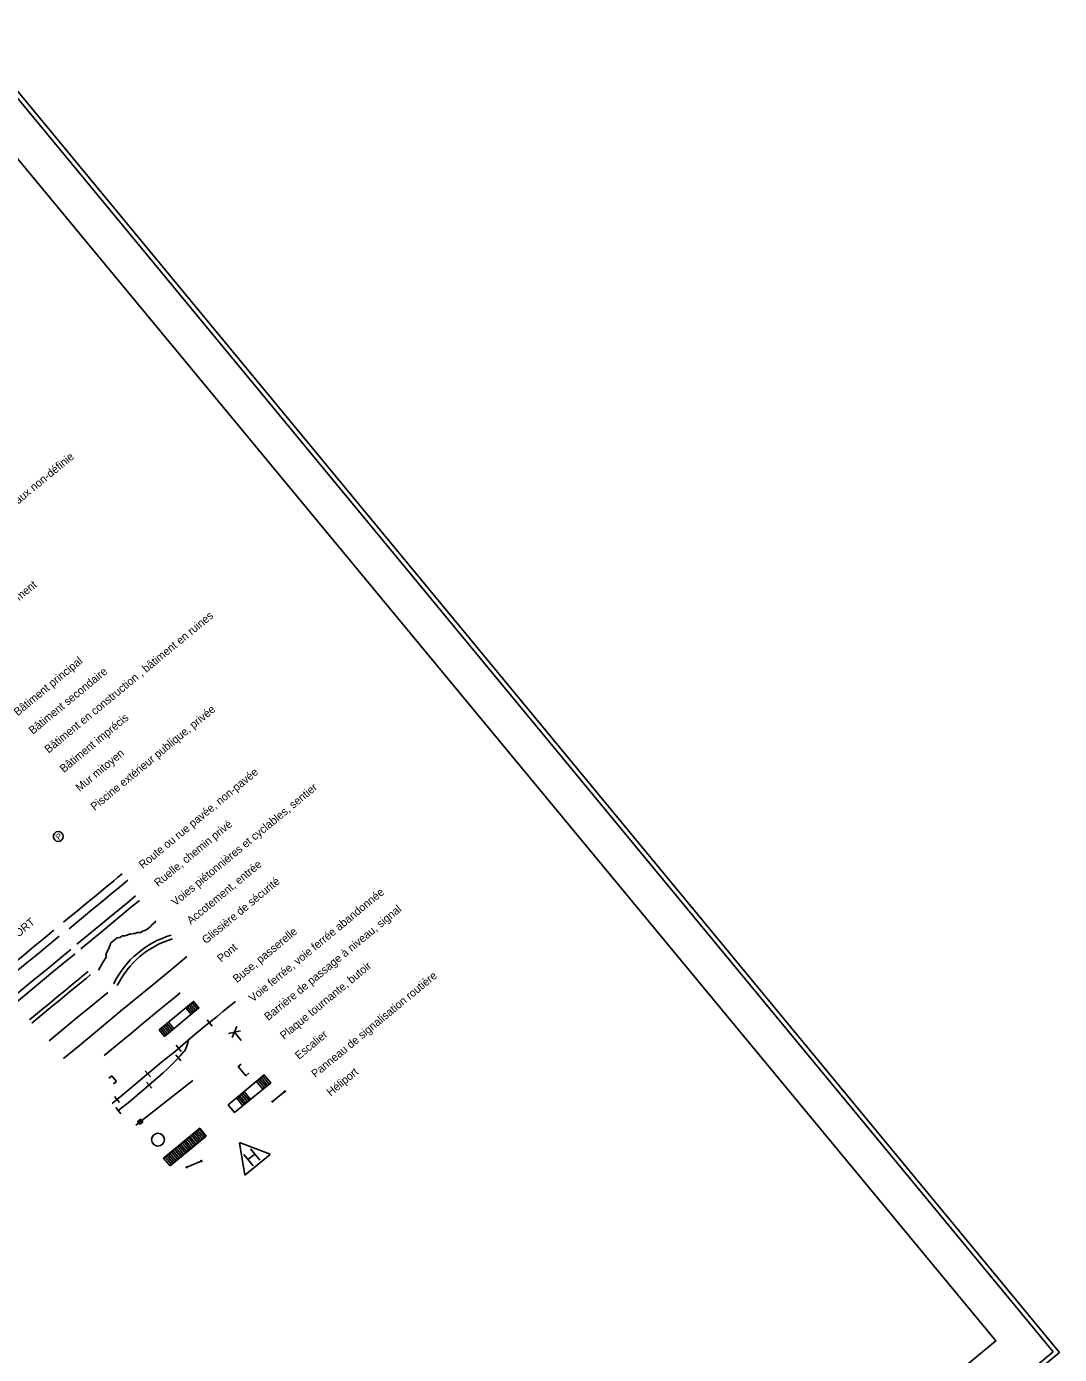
# Model space of a CAD drawing. Extents: x 347059 to 352153, y 6073752 to 6078601.
# Drawn here: x 351379 to 352153, y 6076585 to 6077580 of the extents above; entities that cross this region are included whole.
import ezdxf

# ---------------------------------------------------------------- set-up
doc = ezdxf.new("R2010")
doc.units = 0
for name, color, linetype in [('Level 15', 7, 'Continuous'), ('Level 19', 7, 'Continuous'), ('Level 21', 7, 'Continuous'), ('Level 22', 7, 'Continuous'), ('Level 23', 7, 'Continuous'), ('Level 25', 7, 'Continuous'), ('Level 26', 7, 'Continuous'), ('Level 38', 7, 'Continuous'), ('Level 60', 7, 'Continuous'), ('Level 63', 7, 'Continuous')]:
    doc.layers.add(name, color=color, linetype=linetype)

msp = doc.modelspace()

# ---------------------------------------------------------------- linework, layer by layer
at = {"layer": 'Level 15'}
for p, q in [((351563.37, 6076774.08), (351572.52, 6076781.65)), ((351498.98, 6076724.83), (351509.94, 6076729.48))]:
    msp.add_line(p, q, dxfattribs=at)
for points in [[(351572.46, 6076781.08), (351573.09, 6076781.58), (351572.59, 6076782.19), (351571.95, 6076781.68)], [(351563.3, 6076773.54), (351563.91, 6076774.01), (351563.43, 6076774.62), (351562.8, 6076774.11)], [(351498.77, 6076724.32), (351499.49, 6076724.62), (351499.19, 6076725.34), (351498.47, 6076725.04)], [(351509.73, 6076728.97), (351510.45, 6076729.26), (351510.15, 6076729.98), (351509.4, 6076729.69)]]:
    msp.add_lwpolyline(points, close=True, dxfattribs=at)
at = {"layer": 'Level 19'}
for points in [[(351416.66, 6076891.99), (351430.35, 6076903.36), (351444.34, 6076914.82), (351455.03, 6076923.64), (351460.68, 6076928.3)], [(351419.57, 6076888.48), (351433.26, 6076899.85), (351447.16, 6076911.37), (351457.88, 6076920.19), (351463.5, 6076924.76)]]:
    msp.add_lwpolyline(points, dxfattribs=at)
for radius in [70.21, 67.21]:
    msp.add_arc((351507.33, 6076831.56), radius, 106.46205, 153.98293, dxfattribs=at)
at = {"layer": 'Level 21'}
for points in [[(351406.57, 6076908.48), (351411.22, 6076912.28), (351415.85, 6076916.14), (351423.61, 6076922.53), (351431.32, 6076928.91), (351437.81, 6076934.26), (351444.37, 6076939.66), (351447.42, 6076942.21), (351450.54, 6076944.77)], [(351410.94, 6076903.68), (351415.56, 6076907.54), (351420.22, 6076911.34), (351427.95, 6076917.72), (351435.63, 6076924.07), (351442.18, 6076929.48), (351448.65, 6076934.88), (351451.76, 6076937.44), (351454.87, 6076940.02)], [(351355.35, 6076866.17), (351361, 6076870.87), (351366.69, 6076875.59), (351375.27, 6076882.65), (351383.88, 6076889.75), (351391.55, 6076896.07), (351399.26, 6076902.46)], [(351359.49, 6076861.85), (351365.2, 6076866.54), (351370.88, 6076871.26), (351379.49, 6076878.3), (351388.04, 6076885.39), (351395.75, 6076891.75), (351403.48, 6076898.13)], [(351368.13, 6076851.87), (351381.88, 6076863.22), (351395.81, 6076874.71), (351406.54, 6076883.52), (351412.13, 6076888.13)], [(351371.01, 6076848.4), (351384.7, 6076859.71), (351398.69, 6076871.26), (351409.33, 6076880.02), (351415.04, 6076884.62), (351409.33, 6076880.02), (351398.69, 6076871.26), (351384.7, 6076859.71), (351371.01, 6076848.4)], [(351406.65, 6076806.36), (351418.53, 6076816.22), (351430.49, 6076826.08), (351439.95, 6076833.88), (351449.44, 6076841.75), (351462.88, 6076852.89), (351476.36, 6076863.96), (351487.75, 6076873.4), (351499.17, 6076882.81)], [(351395.78, 6076819.59), (351403.31, 6076825.89), (351410.92, 6076832.12), (351418.36, 6076838.24), (351425.79, 6076844.36), (351432.77, 6076850.12), (351439.75, 6076855.91)]]:
    msp.add_lwpolyline(points, dxfattribs=at)
at = {"layer": 'Level 22'}
for points in [[(351432.75, 6076872.53), (351436.44, 6076878.92), (351438.51, 6076882.44), (351438.54, 6076882.98), (351438.37, 6076883.76), (351438.92, 6076885.55), (351440.63, 6076888.87), (351441.86, 6076892.25), (351441.93, 6076892.73), (351443.14, 6076893.74), (351446.97, 6076896.92), (351448.86, 6076897.08), (351450.82, 6076898.2), (351452.72, 6076898.37), (351454.37, 6076898.83), (351456.6, 6076899.71), (351457.14, 6076899.68), (351459.33, 6076900.08), (351460.41, 6076900.04), (351461.77, 6076900.72), (351463.12, 6076900.89), (351464.68, 6076900.81), (351465.89, 6076901.73), (351467.54, 6076902.26), (351469.8, 6076903.65), (351471.89, 6076905.37), (351473.16, 6076906.86), (351473.73, 6076907.33), (351475.49, 6076908.79), (351475.31, 6076909.57)], [(351381.04, 6076835.29), (351388.62, 6076841.53), (351396.27, 6076847.82), (351401.89, 6076852.48), (351407.54, 6076857.14), (351412.86, 6076861.54), (351418.2, 6076865.93), (351421.62, 6076868.75), (351425, 6076871.54)], [(351382.94, 6076832.97), (351390.55, 6076839.26), (351398.17, 6076845.55), (351403.82, 6076850.16), (351409.41, 6076854.82), (351414.79, 6076859.24), (351420.13, 6076863.64), (351423.55, 6076866.43), (351426.9, 6076869.25)], [(351534.89, 6076765.83), (351561.96, 6076788.16), (351557.12, 6076794.02), (351530.13, 6076771.63), (351534.89, 6076765.83)], [(351558.48, 6076785.34), (351553.64, 6076791.11)], [(351559.63, 6076786.26), (351554.79, 6076792.15)], [(351560.78, 6076787.21), (351556, 6076793.07)], [(351545.79, 6076774.8), (351540.95, 6076780.63)], [(351546.94, 6076775.75), (351542.07, 6076781.61)], [(351556.16, 6076783.38), (351551.32, 6076789.24)], [(351557.37, 6076784.36), (351552.53, 6076790.16)], [(351541.14, 6076770.97), (351536.33, 6076776.83)], [(351542.29, 6076771.92), (351537.51, 6076777.75)], [(351543.44, 6076772.87), (351538.66, 6076778.7)], [(351544.64, 6076773.85), (351539.77, 6076779.68)], [(351486.51, 6076725.93), (351513.58, 6076748.23), (351508.71, 6076754.06), (351481.7, 6076731.73), (351486.51, 6076725.93)], [(351504.84, 6076750.79), (351509.62, 6076744.96)], [(351506.02, 6076751.77), (351510.8, 6076745.94)], [(351507.17, 6076752.75), (351511.98, 6076746.92)], [(351508.32, 6076753.7), (351513.13, 6076747.87)], [(351493.24, 6076741.26), (351498.08, 6076735.4)], [(351494.42, 6076742.21), (351499.2, 6076736.41)], [(351495.57, 6076743.19), (351500.35, 6076737.36)], [(351496.75, 6076744.17), (351501.53, 6076738.28)], [(351497.83, 6076745.09), (351502.67, 6076739.26)], [(351499.04, 6076746.04), (351503.85, 6076740.21)], [(351500.25, 6076747.05), (351504.97, 6076741.16)], [(351501.34, 6076747.94), (351506.15, 6076742.11)], [(351502.52, 6076748.92), (351507.36, 6076743.09)], [(351503.67, 6076749.87), (351508.48, 6076744.01)], [(351482.85, 6076732.68), (351487.72, 6076726.85)], [(351484, 6076733.6), (351488.87, 6076727.8)], [(351485.14, 6076734.58), (351489.98, 6076728.75)], [(351486.35, 6076735.5), (351491.13, 6076729.67)], [(351487.53, 6076736.51), (351492.34, 6076730.68)], [(351488.62, 6076737.46), (351493.46, 6076731.66)], [(351489.8, 6076738.41), (351494.61, 6076732.58)], [(351490.95, 6076739.39), (351495.72, 6076733.53)], [(351492.09, 6076740.31), (351496.9, 6076734.51)]]:
    msp.add_lwpolyline(points, dxfattribs=at)
at = {"layer": 'Level 23'}
for p, q in [((351534.29, 6076825), (351536.64, 6076830.32)), ((351533.54, 6076825.88), (351530.39, 6076825.15)), ((351532.97, 6076822.01), (351534.29, 6076825)), ((351539.22, 6076827.18), (351533.54, 6076825.88)), ((351534.78, 6076826.2), (351539.94, 6076819.94)), ((351465.23, 6076759.83), (351503.47, 6076789.95))]:
    msp.add_line(p, q, dxfattribs=at)
for points in [[(351443.17, 6076772.74), (351454.93, 6076782.48), (351470.64, 6076795.64), (351480.16, 6076803.69), (351490.58, 6076811.97), (351503.85, 6076823.28), (351513.88, 6076831.54), (351521.89, 6076837.92), (351526, 6076841.54), (351530.92, 6076845.34), (351533.31, 6076847.27), (351535.69, 6076849.2)], [(351518.04, 6076830.69), (351514.24, 6076835.34)], [(351447.68, 6076767.3), (351455.2, 6076773.09), (351463.22, 6076780.04), (351472.31, 6076787.79), (351481.38, 6076795.57), (351484.68, 6076798.64), (351487.13, 6076801.05), (351490.67, 6076804.68), (351494.15, 6076808.43), (351496.7, 6076811.25), (351497.3, 6076811.97), (351498.03, 6076813.16), (351498.34, 6076813.85), (351498.61, 6076814.48), (351499.54, 6076817.29), (351500.46, 6076820.1)], [(351494.9, 6076811.6), (351491.1, 6076816.28)], [(351494.66, 6076804.58), (351490.83, 6076809.23)], [(351539.91, 6076802.21), (351537.61, 6076800.31), (351543.34, 6076793.39), (351545.64, 6076795.29)], [(351471.75, 6076792.54), (351467.95, 6076797.07)], [(351472.73, 6076784.07), (351468.9, 6076788.69)], [(351448.64, 6076773.36), (351444.84, 6076777.98)], [(351449.61, 6076764.95), (351445.78, 6076769.6)], [(351460.94, 6076756.48), (351463.09, 6076758.14), (351462.23, 6076759.23), (351464.37, 6076760.89), (351466.03, 6076758.75), (351463.92, 6076757.11), (351463.09, 6076758.14)], [(351462.68, 6076759.22), (351464.34, 6076760.59), (351464.66, 6076760.17), (351463, 6076758.77), (351463.33, 6076758.35), (351465.02, 6076759.62), (351465.29, 6076759.26), (351463.65, 6076757.93), (351463.98, 6076757.53), (351465.58, 6076758.81)]]:
    msp.add_lwpolyline(points, dxfattribs=at)
msp.add_circle((351477.46, 6076745.54), 4.8, dxfattribs=at)
at = {"layer": 'Level 25'}
for p, q in [((351542.46, 6076718.97), (351538.53, 6076743.27)), ((351538.56, 6076743.33), (351561.68, 6076734.55)), ((351541.84, 6076734.33), (351548.7, 6076725.9)), ((351561.65, 6076734.52), (351542.49, 6076718.93)), ((351544.84, 6076730.58), (351550.01, 6076734.77)), ((351546.92, 6076738.55), (351553.78, 6076730.09))]:
    msp.add_line(p, q, dxfattribs=at)
at = {"layer": 'Level 26'}
for p, q in [((351442.81, 6076793.39), (351440.72, 6076791.67)), ((351442.81, 6076793.39), (351446.31, 6076789.19)), ((351446.31, 6076789.19), (351444.2, 6076787.47))]:
    msp.add_line(p, q, dxfattribs=at)
for points in [[(351437.18, 6076808.68), (351444.19, 6076814.44), (351451.17, 6076820.17), (351457.82, 6076825.69), (351464.5, 6076831.24), (351473.23, 6076838.49), (351481.96, 6076845.7), (351488.04, 6076850.69), (351494.17, 6076855.68)], [(351482.34, 6076822.99), (351508.11, 6076844.31), (351504.13, 6076849.11), (351478.36, 6076827.79), (351482.34, 6076822.99)], [(351498.33, 6076844.3), (351502.34, 6076839.53)], [(351499.45, 6076845.31), (351503.49, 6076840.48)], [(351500.6, 6076846.26), (351504.61, 6076841.4)], [(351501.84, 6076847.15), (351505.78, 6076842.38)], [(351502.98, 6076848.16), (351506.99, 6076843.3)], [(351481.86, 6076830.64), (351485.75, 6076825.84)], [(351482.98, 6076831.59), (351486.93, 6076826.85)], [(351484.16, 6076832.54), (351488.08, 6076827.8)], [(351485.28, 6076833.52), (351489.23, 6076828.72)], [(351479.48, 6076828.71), (351483.45, 6076823.94)], [(351480.68, 6076829.69), (351484.6, 6076824.89)]]:
    msp.add_lwpolyline(points, dxfattribs=at)
at = {"layer": 'Level 38'}
msp.add_circle((351402.67, 6076972.78), 3.69, dxfattribs=at)
at = {"layer": 'Level 60'}
for points in [[(350488.06, 6078596.06), (352148.69, 6076586.41)], [(350488.49, 6078600.77), (352153.39, 6076585.96)], [(348723.67, 6073751.88), (352153.39, 6076585.96)], [(348724.12, 6073756.59), (352148.69, 6076586.41)]]:
    msp.add_lwpolyline(points, dxfattribs=at)
msp.add_lwpolyline([(349811.7, 6077991.51), (350486.88, 6078550.39), (352105.73, 6076594.68), (351430.55, 6076035.79)], close=True, dxfattribs=at)

# ---------------------------------------------------------------- texts
at = {"layer": 'Level 38'}
msp.add_text('P', height=4.5, rotation=39.54715, dxfattribs=at).set_placement((351403.02, 6076969.77))
at = {"layer": 'Level 60'}
msp.add_text('TRANSPORT', height=6, rotation=39.54715, dxfattribs=at).set_placement((351347.61, 6076876.19))
at = {"layer": 'Level 63'}
for s, height, p in [('Ligne naturelle des hautes eaux non-définie', 5.9999, (351295.04, 6077157.43)), ('Mur de soutènement', 5.9999, (351330.46, 6077113.68)), ('Bâtiment en construction , bâtiment en ruines', 5.9999, (351395.42, 6077034.85)), ('Bâtiment principal', 5.9999, (351372.32, 6077062.83)), ('Bâtiment secondaire', 5.9999, (351383.63, 6077048.99)), ('Piscine extérieur publique, privée', 5.9999, (351429.94, 6076991.92)), ('Bâtiment imprécis', 5.9999, (351406.85, 6077020.29)), ('Mur mitoyen', 5.9999, (351418.69, 6077006.17)), ('Route ou rue pavée, non-pavée', 5.9999, (351466.11, 6076948.31)), ('Voies piétonnières et cyclables, sentier', 5.9999, (351490.53, 6076920.35)), ('Ruelle, chemin privé', 5.9999, (351477.63, 6076934.8)), ('Accotement, entrée', 5.9999, (351502.11, 6076906.57)), ('Glissière de sécurité', 5.9999, (351513.41, 6076891.95)), ('Voie ferrée, voie ferrée abandonnée', 5.9999, (351548.62, 6076848.33)), ('Barrière de passage à niveau, signal', 5.9999, (351560.17, 6076834.49)), ('Buse, passerelle', 5.9999, (351536.68, 6076862.8)), ('Pont', 6, (351524.87, 6076878.11)), ('Plaque tournante, butoir', 5.9999, (351571.99, 6076820.37)), ('Panneau de signalisation routière', 5.9999, (351595.44, 6076791.67)), ('Escalier', 6, (351583.23, 6076805.28)), ('Héliport', 6, (351606.93, 6076777.8))]:
    msp.add_text(s, height=height, rotation=39.54715, dxfattribs=at).set_placement(p)

doc.saveas('drawing.dxf')
